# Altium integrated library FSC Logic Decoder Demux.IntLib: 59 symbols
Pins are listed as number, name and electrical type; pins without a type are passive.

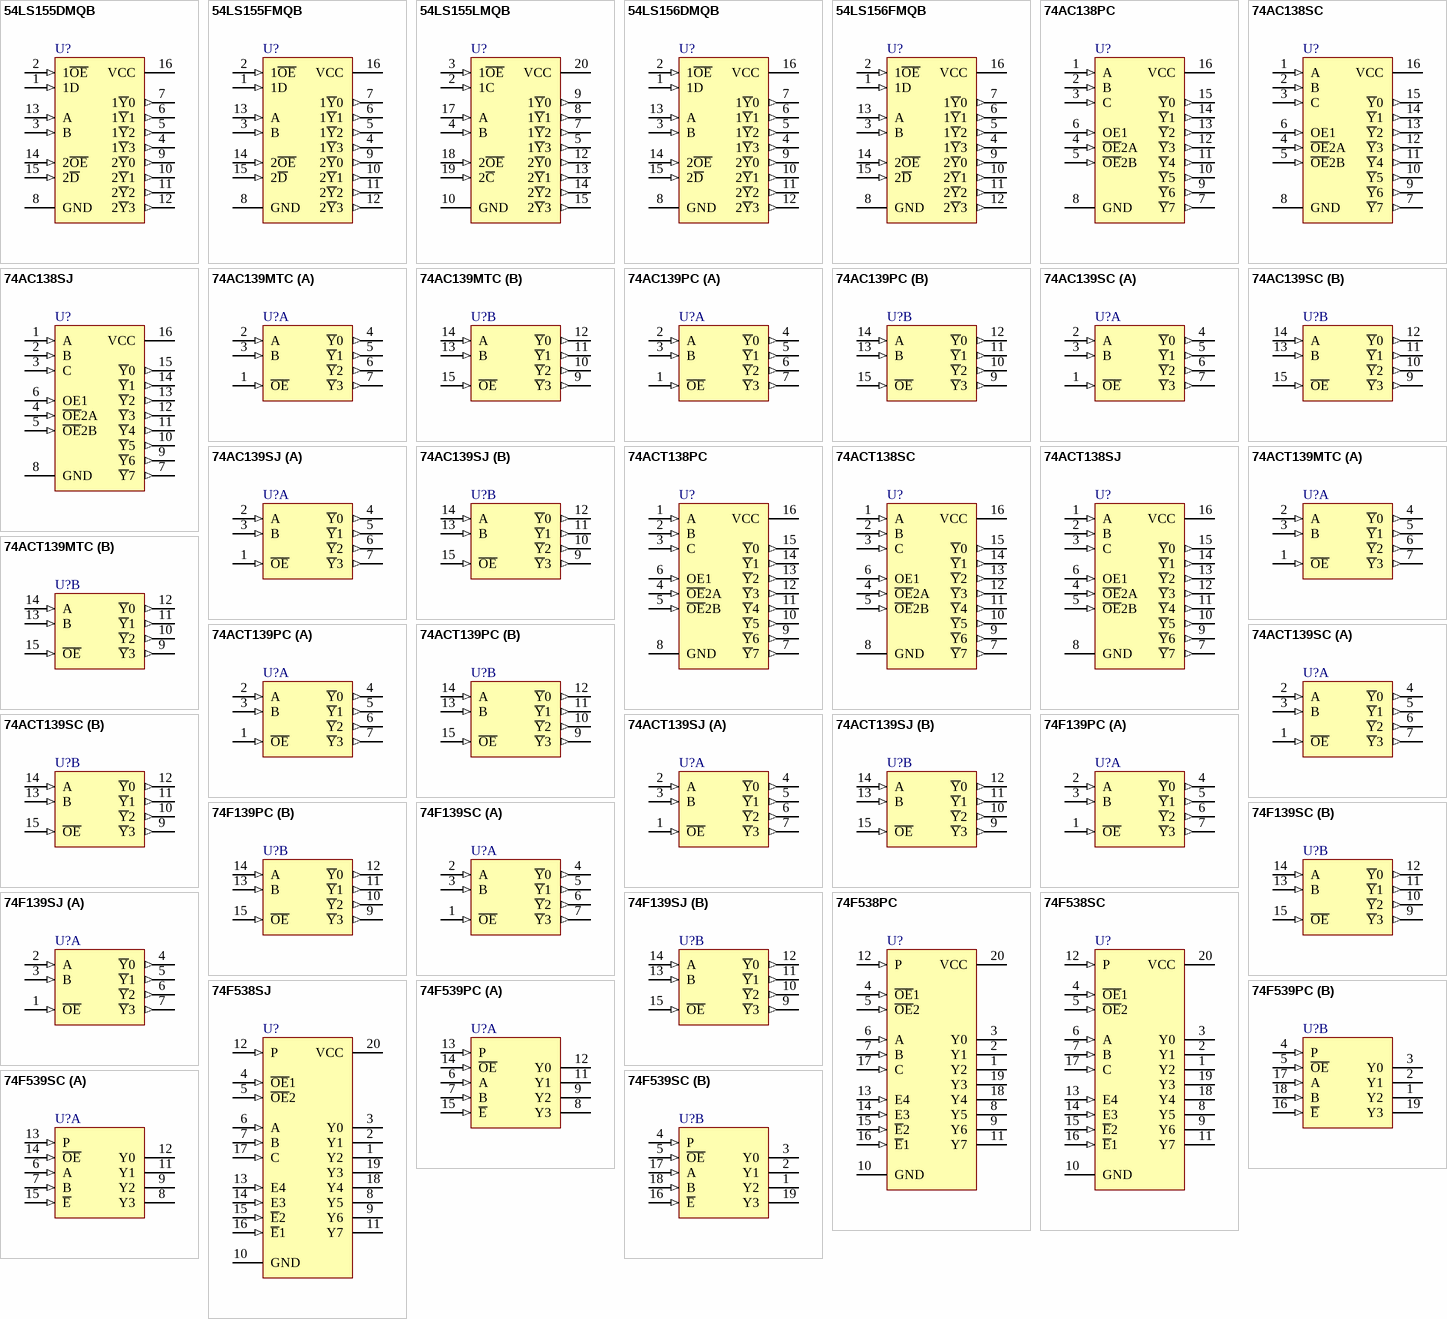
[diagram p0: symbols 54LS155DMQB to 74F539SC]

## 54LS155DMQB
designator U?
Dual 2-Line to 4-Line Decoder/Demultiplexer; Note: Generic Simulation model provided.
footprint J16A (DIP, 16-Leads, Row Spacing 7.62mm, Pitch 2.54mm, Body 19.56x6.73mm)
3D model N16E (CerDIP, 16-Pin, Row Spacing 7.62 mm, Pitch 2.54 mm)
simulation model 74LS155 (SIMCODE)
signal-integrity model 54LS155DMQB
pins: 1 1D (in), 2 1~{OE} (in), 3 B (in), 4 1~{Y}3 (out), 5 1~{Y}2 (out), 6 1~{Y}1 (out), 7 1~{Y}0 (out), 8 GND (power), 9 2~{Y}0 (out), 10 2~{Y}1 (out), 11 2~{Y}2 (out), 12 2~{Y}3 (out), 13 A (in), 14 2~{OE} (in), 15 2~{D} (in), 16 VCC (power)

## 54LS155FMQB
designator U?
Dual 2-Line to 4-Line Decoder/Demultiplexer; Note: Generic Simulation model provided.
footprint W16A (DFP; 16 Leads; Body 9.9 x 7.6 mm (LxW max); Pitch 1.27 mm)
3D model W16A (DFP; 16 Leads; Body 9.9 x 7.6 mm (LxW max); Pitch 1.27 mm)
simulation model 74LS155 (SIMCODE)
signal-integrity model 54LS155FMQB
pins: 1 1D (in), 2 1~{OE} (in), 3 B (in), 4 1~{Y}3 (out), 5 1~{Y}2 (out), 6 1~{Y}1 (out), 7 1~{Y}0 (out), 8 GND (power), 9 2~{Y}0 (out), 10 2~{Y}1 (out), 11 2~{Y}2 (out), 12 2~{Y}3 (out), 13 A (in), 14 2~{OE} (in), 15 2~{D} (in), 16 VCC (power)

## 54LS155LMQB
designator U?
Dual 2-Line to 4-Line Decoder/Demultiplexer; Note: Pins 1, 6, 11, and 16 are 'No Connect'.
footprint E20A (Leadless Chip Carrier; 20 Terminals; Body 8.9 x 8.9 mm)
footprint E20A_N (Leadless Chip Carrier, 20-Leads, Body 8.9x8.9mm, Pitch 1.27mm, IPC Medium Density)
footprint E20A_L (Leadless Chip Carrier, 20-Leads, Body 8.9x8.9mm, Pitch 1.27mm, IPC High Density)
footprint E20A_M (Leadless Chip Carrier, 20-Leads, Body 8.9x8.9mm, Pitch 1.27mm, IPC Low Density)
simulation model 74LS155 (SIMCODE)
signal-integrity model 54LS155LMQB
pins: 2 1C (in), 3 1~{OE} (in), 4 B (in), 5 1~{Y}3 (out), 7 1~{Y}2 (out), 8 1~{Y}1 (out), 9 1~{Y}0 (out), 10 GND (power), 12 2~{Y}0 (out), 13 2~{Y}1 (out), 14 2~{Y}2 (out), 15 2~{Y}3 (out), 17 A (in), 18 2~{OE} (in), 19 2~{C} (in), 20 VCC (power)

## 54LS156DMQB
designator U?
Dual 2-Line to 4-Line Decoder/Demultiplexer; Note: Generic Simulation model provided.
footprint J16A (DIP, 16-Leads, Row Spacing 7.62mm, Pitch 2.54mm, Body 19.56x6.73mm)
3D model N16E (CerDIP, 16-Pin, Row Spacing 7.62 mm, Pitch 2.54 mm)
simulation model 74LS156 (SIMCODE)
signal-integrity model 54LS156DMQB
pins: 1 1D (in), 2 1~{OE} (in), 3 B (in), 4 1~{Y}3 (out), 5 1~{Y}2 (out), 6 1~{Y}1 (out), 7 1~{Y}0 (out), 8 GND (power), 9 2~{Y}0 (out), 10 2~{Y}1 (out), 11 2~{Y}2 (out), 12 2~{Y}3 (out), 13 A (in), 14 2~{OE} (in), 15 2~{D} (in), 16 VCC (power)

## 54LS156FMQB
designator U?
Dual 2-Line to 4-Line Decoder/Demultiplexer; Note: Generic Simulation model provided.
footprint W16A (DFP; 16 Leads; Body 9.9 x 7.6 mm (LxW max); Pitch 1.27 mm)
3D model W16A (DFP; 16 Leads; Body 9.9 x 7.6 mm (LxW max); Pitch 1.27 mm)
simulation model 74LS156 (SIMCODE)
signal-integrity model 54LS156FMQB
pins: 1 1D (in), 2 1~{OE} (in), 3 B (in), 4 1~{Y}3 (out), 5 1~{Y}2 (out), 6 1~{Y}1 (out), 7 1~{Y}0 (out), 8 GND (power), 9 2~{Y}0 (out), 10 2~{Y}1 (out), 11 2~{Y}2 (out), 12 2~{Y}3 (out), 13 A (in), 14 2~{OE} (in), 15 2~{D} (in), 16 VCC (power)

## 74AC138PC
designator U?
1-of-8 Decoder/Multiplexer
footprint N16E (DIP, 16-Leads, Row Spacing 7.62mm, Pitch 2.54mm, Body 19.3x6.35mm)
3D model N16E (DIP, 16-Pin, Row Spacing 7.62 mm, Pitch 2.54 mm)
signal-integrity model 74AC138PC
pins: 1 A (in), 2 B (in), 3 C (in), 4 ~{OE}2A (in), 5 ~{OE}2B (in), 6 OE1 (in), 7 ~{Y}7 (out), 8 GND (power), 9 ~{Y}6 (out), 10 ~{Y}5 (out), 11 ~{Y}4 (out), 12 ~{Y}3 (out), 13 ~{Y}2 (out), 14 ~{Y}1 (out), 15 ~{Y}0 (out), 16 VCC (power)

## 74AC138SC
designator U?
1-of-8 Decoder/Multiplexer
footprint M16A_N (SOIC, 16-Leads, Body 9.9x3.9mm, Pitch 1.27mm, IPC Medium Density)
footprint M16A_L (SOIC, 16-Leads, Body 9.9x3.9mm, Pitch 1.27mm, IPC High Density)
footprint M16A_M (SOIC, 16-Leads, Body 9.9x3.9mm, Pitch 1.27mm, IPC Low Density)
3D model M16A (16-Pin Small Outline Integrated Circuit 1.27 mm Pitch)
signal-integrity model 74AC138SC
pins: 1 A (in), 2 B (in), 3 C (in), 4 ~{OE}2A (in), 5 ~{OE}2B (in), 6 OE1 (in), 7 ~{Y}7 (out), 8 GND (power), 9 ~{Y}6 (out), 10 ~{Y}5 (out), 11 ~{Y}4 (out), 12 ~{Y}3 (out), 13 ~{Y}2 (out), 14 ~{Y}1 (out), 15 ~{Y}0 (out), 16 VCC (power)

## 74AC138SJ
designator U?
1-of-8 Decoder/Multiplexer
footprint M16D_N (SOP, 16-Leads, Body 10.1x5.3mm, Pitch 1.27mm, IPC Medium Density)
footprint M16D_L (SOP, 16-Leads, Body 10.1x5.3mm, Pitch 1.27mm, IPC High Density)
footprint M16D_M (SOP, 16-Leads, Body 10.1x5.3mm, Pitch 1.27mm, IPC Low Density)
3D model M16D (16-Pin Small Outline Package 1.27 mm Pitch)
signal-integrity model 74AC138SJ
pins: 1 A (in), 2 B (in), 3 C (in), 4 ~{OE}2A (in), 5 ~{OE}2B (in), 6 OE1 (in), 7 ~{Y}7 (out), 8 GND (power), 9 ~{Y}6 (out), 10 ~{Y}5 (out), 11 ~{Y}4 (out), 12 ~{Y}3 (out), 13 ~{Y}2 (out), 14 ~{Y}1 (out), 15 ~{Y}0 (out), 16 VCC (power)

## 74AC139MTC
designator U?
Dual 1-of-4 Decoder/Demultiplexer; Note: Generic Simulation model provided.
footprint MTC16_N (TSOP, 16-Leads, Body 5x4.4mm, Pitch 0.65mm, IPC Medium Density)
footprint MTC16_L (TSOP, 16-Leads, Body 5x4.4mm, Pitch 0.65mm, IPC High Density)
footprint MTC16_M (TSOP, 16-Leads, Body 5x4.4mm, Pitch 0.65mm, IPC Low Density)
3D model MTC16 (16-Pin Thin Small Outline Package 0.65 mm Pitch)
simulation model 74LS139 (SIMCODE)
signal-integrity model 74AC139MTC
pins on every part: 8 GND (power) hidden to GND, 16 VCC (power) hidden to VCC
part A pins: 1 ~{OE} (in), 2 A (in), 3 B (in), 4 ~{Y}0 (out), 5 ~{Y}1 (out), 6 ~{Y}2 (out), 7 ~{Y}3 (out)
part B pins: 9 ~{Y}3 (out), 10 ~{Y}2 (out), 11 ~{Y}1 (out), 12 ~{Y}0 (out), 13 B (in), 14 A (in), 15 ~{OE} (in)

## 74AC139PC
designator U?
Dual 1-of-4 Decoder/Demultiplexer; Note: Generic Simulation model provided.
footprint N16E (DIP, 16-Leads, Row Spacing 7.62mm, Pitch 2.54mm, Body 19.3x6.35mm)
3D model N16E (DIP, 16-Pin, Row Spacing 7.62 mm, Pitch 2.54 mm)
simulation model 74LS139 (SIMCODE)
signal-integrity model 74AC139PC
pins on every part: 8 GND (power) hidden to GND, 16 VCC (power) hidden to VCC
part A pins: 1 ~{OE} (in), 2 A (in), 3 B (in), 4 ~{Y}0 (out), 5 ~{Y}1 (out), 6 ~{Y}2 (out), 7 ~{Y}3 (out)
part B pins: 9 ~{Y}3 (out), 10 ~{Y}2 (out), 11 ~{Y}1 (out), 12 ~{Y}0 (out), 13 B (in), 14 A (in), 15 ~{OE} (in)

## 74AC139SC
designator U?
Dual 1-of-4 Decoder/Demultiplexer; Note: Generic Simulation model provided.
footprint M16A_N (SOIC, 16-Leads, Body 9.9x3.9mm, Pitch 1.27mm, IPC Medium Density)
footprint M16A_L (SOIC, 16-Leads, Body 9.9x3.9mm, Pitch 1.27mm, IPC High Density)
footprint M16A_M (SOIC, 16-Leads, Body 9.9x3.9mm, Pitch 1.27mm, IPC Low Density)
3D model M16A (16-Pin Small Outline Integrated Circuit 1.27 mm Pitch)
simulation model 74LS139 (SIMCODE)
signal-integrity model 74AC139SC
pins on every part: 8 GND (power) hidden to GND, 16 VCC (power) hidden to VCC
part A pins: 1 ~{OE} (in), 2 A (in), 3 B (in), 4 ~{Y}0 (out), 5 ~{Y}1 (out), 6 ~{Y}2 (out), 7 ~{Y}3 (out)
part B pins: 9 ~{Y}3 (out), 10 ~{Y}2 (out), 11 ~{Y}1 (out), 12 ~{Y}0 (out), 13 B (in), 14 A (in), 15 ~{OE} (in)

## 74AC139SJ
designator U?
Dual 1-of-4 Decoder/Demultiplexer; Note: Generic Simulation model provided.
footprint M16D_N (SOP, 16-Leads, Body 10.1x5.3mm, Pitch 1.27mm, IPC Medium Density)
footprint M16D_L (SOP, 16-Leads, Body 10.1x5.3mm, Pitch 1.27mm, IPC High Density)
footprint M16D_M (SOP, 16-Leads, Body 10.1x5.3mm, Pitch 1.27mm, IPC Low Density)
3D model M16D (16-Pin Small Outline Package 1.27 mm Pitch)
simulation model 74LS139 (SIMCODE)
signal-integrity model 74AC139SJ
pins on every part: 8 GND (power) hidden to GND, 16 VCC (power) hidden to VCC
part A pins: 1 ~{OE} (in), 2 A (in), 3 B (in), 4 ~{Y}0 (out), 5 ~{Y}1 (out), 6 ~{Y}2 (out), 7 ~{Y}3 (out)
part B pins: 9 ~{Y}3 (out), 10 ~{Y}2 (out), 11 ~{Y}1 (out), 12 ~{Y}0 (out), 13 B (in), 14 A (in), 15 ~{OE} (in)

## 74ACT138PC
designator U?
1-of-8 Decoder/Multiplexer
footprint N16E (DIP, 16-Leads, Row Spacing 7.62mm, Pitch 2.54mm, Body 19.3x6.35mm)
3D model N16E (DIP, 16-Pin, Row Spacing 7.62 mm, Pitch 2.54 mm)
signal-integrity model 74ACT138PC
pins: 1 A (in), 2 B (in), 3 C (in), 4 ~{OE}2A (in), 5 ~{OE}2B (in), 6 OE1 (in), 7 ~{Y}7 (out), 8 GND (power), 9 ~{Y}6 (out), 10 ~{Y}5 (out), 11 ~{Y}4 (out), 12 ~{Y}3 (out), 13 ~{Y}2 (out), 14 ~{Y}1 (out), 15 ~{Y}0 (out), 16 VCC (power)

## 74ACT138SC
designator U?
1-of-8 Decoder/Multiplexer
footprint M16A_N (SOIC, 16-Leads, Body 9.9x3.9mm, Pitch 1.27mm, IPC Medium Density)
footprint M16A_L (SOIC, 16-Leads, Body 9.9x3.9mm, Pitch 1.27mm, IPC High Density)
footprint M16A_M (SOIC, 16-Leads, Body 9.9x3.9mm, Pitch 1.27mm, IPC Low Density)
3D model M16A (16-Pin Small Outline Integrated Circuit 1.27 mm Pitch)
signal-integrity model 74ACT138SC
pins: 1 A (in), 2 B (in), 3 C (in), 4 ~{OE}2A (in), 5 ~{OE}2B (in), 6 OE1 (in), 7 ~{Y}7 (out), 8 GND (power), 9 ~{Y}6 (out), 10 ~{Y}5 (out), 11 ~{Y}4 (out), 12 ~{Y}3 (out), 13 ~{Y}2 (out), 14 ~{Y}1 (out), 15 ~{Y}0 (out), 16 VCC (power)

## 74ACT138SJ
designator U?
1-of-8 Decoder/Multiplexer
footprint M16D_N (SOP, 16-Leads, Body 10.1x5.3mm, Pitch 1.27mm, IPC Medium Density)
footprint M16D_L (SOP, 16-Leads, Body 10.1x5.3mm, Pitch 1.27mm, IPC High Density)
footprint M16D_M (SOP, 16-Leads, Body 10.1x5.3mm, Pitch 1.27mm, IPC Low Density)
3D model M16D (16-Pin Small Outline Package 1.27 mm Pitch)
signal-integrity model 74ACT138SJ
pins: 1 A (in), 2 B (in), 3 C (in), 4 ~{OE}2A (in), 5 ~{OE}2B (in), 6 OE1 (in), 7 ~{Y}7 (out), 8 GND (power), 9 ~{Y}6 (out), 10 ~{Y}5 (out), 11 ~{Y}4 (out), 12 ~{Y}3 (out), 13 ~{Y}2 (out), 14 ~{Y}1 (out), 15 ~{Y}0 (out), 16 VCC (power)

## 74ACT139MTC
designator U?
Dual 1-of-4 Decoder/Demultiplexer; Note: Generic Simulation model provided.
footprint MTC16_N (TSOP, 16-Leads, Body 5x4.4mm, Pitch 0.65mm, IPC Medium Density)
footprint MTC16_L (TSOP, 16-Leads, Body 5x4.4mm, Pitch 0.65mm, IPC High Density)
footprint MTC16_M (TSOP, 16-Leads, Body 5x4.4mm, Pitch 0.65mm, IPC Low Density)
3D model MTC16 (16-Pin Thin Small Outline Package 0.65 mm Pitch)
simulation model 74LS139 (SIMCODE)
signal-integrity model 74ACT139MTC
pins on every part: 8 GND (power) hidden to GND, 16 VCC (power) hidden to VCC
part A pins: 1 ~{OE} (in), 2 A (in), 3 B (in), 4 ~{Y}0 (out), 5 ~{Y}1 (out), 6 ~{Y}2 (out), 7 ~{Y}3 (out)
part B pins: 9 ~{Y}3 (out), 10 ~{Y}2 (out), 11 ~{Y}1 (out), 12 ~{Y}0 (out), 13 B (in), 14 A (in), 15 ~{OE} (in)

## 74ACT139PC
designator U?
Dual 1-of-4 Decoder/Demultiplexer; Note: Generic Simulation model provided.
footprint N16E (DIP, 16-Leads, Row Spacing 7.62mm, Pitch 2.54mm, Body 19.3x6.35mm)
3D model N16E (DIP, 16-Pin, Row Spacing 7.62 mm, Pitch 2.54 mm)
simulation model 74LS139 (SIMCODE)
signal-integrity model 74ACT139PC
pins on every part: 8 GND (power) hidden to GND, 16 VCC (power) hidden to VCC
part A pins: 1 ~{OE} (in), 2 A (in), 3 B (in), 4 ~{Y}0 (out), 5 ~{Y}1 (out), 6 ~{Y}2 (out), 7 ~{Y}3 (out)
part B pins: 9 ~{Y}3 (out), 10 ~{Y}2 (out), 11 ~{Y}1 (out), 12 ~{Y}0 (out), 13 B (in), 14 A (in), 15 ~{OE} (in)

## 74ACT139SC
designator U?
Dual 1-of-4 Decoder/Demultiplexer; Note: Generic Simulation model provided.
footprint M16A_N (SOIC, 16-Leads, Body 9.9x3.9mm, Pitch 1.27mm, IPC Medium Density)
footprint M16A_L (SOIC, 16-Leads, Body 9.9x3.9mm, Pitch 1.27mm, IPC High Density)
footprint M16A_M (SOIC, 16-Leads, Body 9.9x3.9mm, Pitch 1.27mm, IPC Low Density)
3D model M16A (16-Pin Small Outline Integrated Circuit 1.27 mm Pitch)
simulation model 74LS139 (SIMCODE)
signal-integrity model 74ACT139SC
pins on every part: 8 GND (power) hidden to GND, 16 VCC (power) hidden to VCC
part A pins: 1 ~{OE} (in), 2 A (in), 3 B (in), 4 ~{Y}0 (out), 5 ~{Y}1 (out), 6 ~{Y}2 (out), 7 ~{Y}3 (out)
part B pins: 9 ~{Y}3 (out), 10 ~{Y}2 (out), 11 ~{Y}1 (out), 12 ~{Y}0 (out), 13 B (in), 14 A (in), 15 ~{OE} (in)

## 74ACT139SJ
designator U?
Dual 1-of-4 Decoder/Demultiplexer; Note: Generic Simulation model provided.
footprint M16D_N (SOP, 16-Leads, Body 10.1x5.3mm, Pitch 1.27mm, IPC Medium Density)
footprint M16D_L (SOP, 16-Leads, Body 10.1x5.3mm, Pitch 1.27mm, IPC High Density)
footprint M16D_M (SOP, 16-Leads, Body 10.1x5.3mm, Pitch 1.27mm, IPC Low Density)
3D model M16D (16-Pin Small Outline Package 1.27 mm Pitch)
simulation model 74LS139 (SIMCODE)
signal-integrity model 74ACT139SJ
pins on every part: 8 GND (power) hidden to GND, 16 VCC (power) hidden to VCC
part A pins: 1 ~{OE} (in), 2 A (in), 3 B (in), 4 ~{Y}0 (out), 5 ~{Y}1 (out), 6 ~{Y}2 (out), 7 ~{Y}3 (out)
part B pins: 9 ~{Y}3 (out), 10 ~{Y}2 (out), 11 ~{Y}1 (out), 12 ~{Y}0 (out), 13 B (in), 14 A (in), 15 ~{OE} (in)

## 74F139PC
designator U?
Dual 1-of-4 Decoder/Demultiplexer; Note: Generic Simulation model provided.
footprint N16E (DIP, 16-Leads, Row Spacing 7.62mm, Pitch 2.54mm, Body 19.3x6.35mm)
3D model N16E (DIP, 16-Pin, Row Spacing 7.62 mm, Pitch 2.54 mm)
simulation model 74LS139 (SIMCODE)
signal-integrity model 74F139PC
pins on every part: 8 GND (power) hidden to GND, 16 VCC (power) hidden to VCC
part A pins: 1 ~{OE} (in), 2 A (in), 3 B (in), 4 ~{Y}0 (out), 5 ~{Y}1 (out), 6 ~{Y}2 (out), 7 ~{Y}3 (out)
part B pins: 9 ~{Y}3 (out), 10 ~{Y}2 (out), 11 ~{Y}1 (out), 12 ~{Y}0 (out), 13 B (in), 14 A (in), 15 ~{OE} (in)

## 74F139SC
designator U?
Dual 1-of-4 Decoder/Demultiplexer; Note: Generic Simulation model provided.
footprint M16A_N (SOIC, 16-Leads, Body 9.9x3.9mm, Pitch 1.27mm, IPC Medium Density)
footprint M16A_L (SOIC, 16-Leads, Body 9.9x3.9mm, Pitch 1.27mm, IPC High Density)
footprint M16A_M (SOIC, 16-Leads, Body 9.9x3.9mm, Pitch 1.27mm, IPC Low Density)
3D model M16A (16-Pin Small Outline Integrated Circuit 1.27 mm Pitch)
simulation model 74LS139 (SIMCODE)
signal-integrity model 74F139SC
pins on every part: 8 GND (power) hidden to GND, 16 VCC (power) hidden to VCC
part A pins: 1 ~{OE} (in), 2 A (in), 3 B (in), 4 ~{Y}0 (out), 5 ~{Y}1 (out), 6 ~{Y}2 (out), 7 ~{Y}3 (out)
part B pins: 9 ~{Y}3 (out), 10 ~{Y}2 (out), 11 ~{Y}1 (out), 12 ~{Y}0 (out), 13 B (in), 14 A (in), 15 ~{OE} (in)

## 74F139SJ
designator U?
Dual 1-of-4 Decoder/Demultiplexer; Note: Generic Simulation model provided.
footprint M16D_N (SOP, 16-Leads, Body 10.1x5.3mm, Pitch 1.27mm, IPC Medium Density)
footprint M16D_L (SOP, 16-Leads, Body 10.1x5.3mm, Pitch 1.27mm, IPC High Density)
footprint M16D_M (SOP, 16-Leads, Body 10.1x5.3mm, Pitch 1.27mm, IPC Low Density)
3D model M16D (16-Pin Small Outline Package 1.27 mm Pitch)
simulation model 74LS139 (SIMCODE)
signal-integrity model 74F139SJ
pins on every part: 8 GND (power) hidden to GND, 16 VCC (power) hidden to VCC
part A pins: 1 ~{OE} (in), 2 A (in), 3 B (in), 4 ~{Y}0 (out), 5 ~{Y}1 (out), 6 ~{Y}2 (out), 7 ~{Y}3 (out)
part B pins: 9 ~{Y}3 (out), 10 ~{Y}2 (out), 11 ~{Y}1 (out), 12 ~{Y}0 (out), 13 B (in), 14 A (in), 15 ~{OE} (in)

## 74F538PC
designator U?
1-of-8 Decoder with 3-State Output
footprint N20A (DIP, 20-Leads, Row Spacing 7.62mm, Pitch 2.54mm, Body 26.07x6.6mm)
3D model N20A (DIP, 20-Pin, Row Spacing 7.62 mm, Pitch 2.54 mm)
signal-integrity model 74F538PC
pins: 1 Y2 (hiz), 2 Y1 (hiz), 3 Y0 (hiz), 4 ~{OE}1 (in), 5 ~{OE}2 (in), 6 A (in), 7 B (in), 8 Y5 (hiz), 9 Y6 (hiz), 10 GND (power), 11 Y7 (hiz), 12 P (in), 13 E4 (in), 14 E3 (in), 15 ~{E}2 (in), 16 ~{E}1 (in), 17 C (in), 18 Y4 (hiz), 19 Y3 (hiz), 20 VCC (power)

## 74F538SC
designator U?
1-of-8 Decoder with 3-State Output
footprint M20B_N (SOIC, 20-Leads, Body 12.8x7.5mm, Pitch 1.27mm, IPC Medium Density)
footprint M20B_L (SOIC, 20-Leads, Body 12.8x7.5mm, Pitch 1.27mm, IPC High Density)
footprint M20B_M (SOIC, 20-Leads, Body 12.8x7.5mm, Pitch 1.27mm, IPC Low Density)
3D model M20B (20-Pin Small Outline Integrated Circuit 1.27 mm Pitch)
signal-integrity model 74F538SC
pins: 1 Y2 (hiz), 2 Y1 (hiz), 3 Y0 (hiz), 4 ~{OE}1 (in), 5 ~{OE}2 (in), 6 A (in), 7 B (in), 8 Y5 (hiz), 9 Y6 (hiz), 10 GND (power), 11 Y7 (hiz), 12 P (in), 13 E4 (in), 14 E3 (in), 15 ~{E}2 (in), 16 ~{E}1 (in), 17 C (in), 18 Y4 (hiz), 19 Y3 (hiz), 20 VCC (power)

## 74F538SJ
designator U?
1-of-8 Decoder with 3-State Output
footprint M20D_N (SOP, 20-Leads, Body 12.6x5.3mm, Pitch 1.27mm, IPC Medium Density)
footprint M20D_L (SOP, 20-Leads, Body 12.6x5.3mm, Pitch 1.27mm, IPC High Density)
footprint M20D_M (SOP, 20-Leads, Body 12.6x5.3mm, Pitch 1.27mm, IPC Low Density)
3D model M20D (20-Pin Small Outline Package 1.27 mm Pitch)
signal-integrity model 74F538SJ
pins: 1 Y2 (hiz), 2 Y1 (hiz), 3 Y0 (hiz), 4 ~{OE}1 (in), 5 ~{OE}2 (in), 6 A (in), 7 B (in), 8 Y5 (hiz), 9 Y6 (hiz), 10 GND (power), 11 Y7 (hiz), 12 P (in), 13 E4 (in), 14 E3 (in), 15 ~{E}2 (in), 16 ~{E}1 (in), 17 C (in), 18 Y4 (hiz), 19 Y3 (hiz), 20 VCC (power)

## 74F539PC
designator U?
Dual 1-of-4 Decoder with 3-State Output
footprint N20A (DIP, 20-Leads, Row Spacing 7.62mm, Pitch 2.54mm, Body 26.07x6.6mm)
3D model N20A (DIP, 20-Pin, Row Spacing 7.62 mm, Pitch 2.54 mm)
signal-integrity model 74F539PC
pins on every part: 10 GND (power) hidden to GND, 20 VCC (power) hidden to VCC
part A pins: 6 A (in), 7 B (in), 8 Y3 (hiz), 9 Y2 (hiz), 11 Y1 (hiz), 12 Y0 (hiz), 13 P (in), 14 ~{OE} (in), 15 ~{E} (in)
part B pins: 1 Y2 (hiz), 2 Y1 (hiz), 3 Y0 (hiz), 4 P (in), 5 ~{OE} (in), 16 ~{E} (in), 17 A (in), 18 B (in), 19 Y3 (hiz)

## 74F539SC
designator U?
Dual 1-of-4 Decoder with 3-State Output
footprint M20B_N (SOIC, 20-Leads, Body 12.8x7.5mm, Pitch 1.27mm, IPC Medium Density)
footprint M20B_L (SOIC, 20-Leads, Body 12.8x7.5mm, Pitch 1.27mm, IPC High Density)
footprint M20B_M (SOIC, 20-Leads, Body 12.8x7.5mm, Pitch 1.27mm, IPC Low Density)
3D model M20B (20-Pin Small Outline Integrated Circuit 1.27 mm Pitch)
signal-integrity model 74F539SC
pins on every part: 10 GND (power) hidden to GND, 20 VCC (power) hidden to VCC
part A pins: 6 A (in), 7 B (in), 8 Y3 (hiz), 9 Y2 (hiz), 11 Y1 (hiz), 12 Y0 (hiz), 13 P (in), 14 ~{OE} (in), 15 ~{E} (in)
part B pins: 1 Y2 (hiz), 2 Y1 (hiz), 3 Y0 (hiz), 4 P (in), 5 ~{OE} (in), 16 ~{E} (in), 17 A (in), 18 B (in), 19 Y3 (hiz)

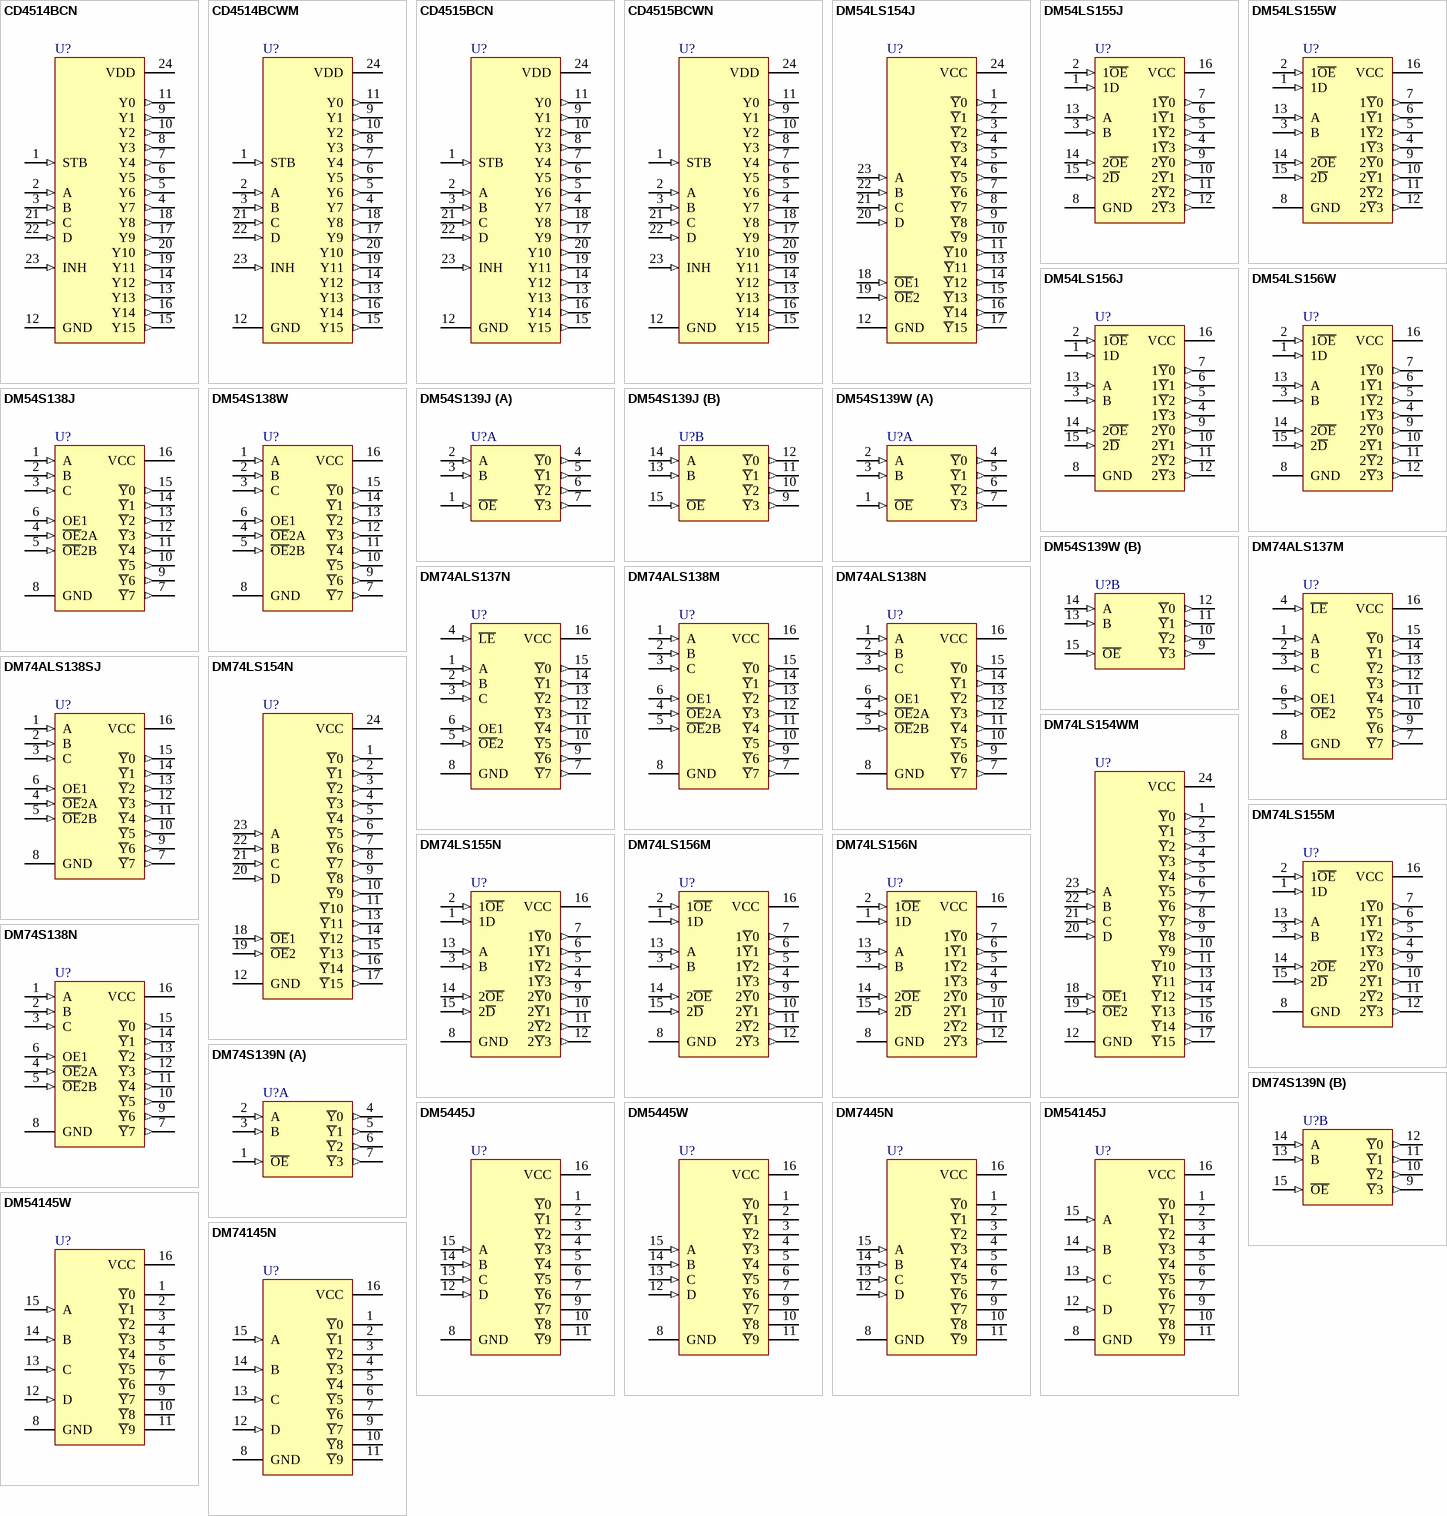
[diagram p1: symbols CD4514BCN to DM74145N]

## CD4514BCN
designator U?
4 Bit Latched/4-to-16-Line Decoder
footprint N24A (DIP, 24-Leads, Row Spacing 15.24mm, Pitch 2.54mm, Body 31.92x13.72mm)
3D model N24A (DIP, 24-Pin, Row Spacing 15.24 mm, Pitch 2.54 mm)
pins: 1 STB (in), 2 A (in), 3 B (in), 4 Y7 (out), 5 Y6 (out), 6 Y5 (out), 7 Y4 (out), 8 Y3 (out), 9 Y1 (out), 10 Y2 (out), 11 Y0 (out), 12 GND (power), 13 Y13 (out), 14 Y12 (out), 15 Y15 (out), 16 Y14 (out), 17 Y9 (out), 18 Y8 (out), 19 Y11 (out), 20 Y10 (out), 21 C (in), 22 D (in), 23 INH (in), 24 VDD (power)

## CD4514BCWM
designator U?
4 Bit Latched/4-to-16-Line Decoder
footprint M24B_N (SOIC, 24-Leads, Body 15.4x7.5mm, Pitch 1.27mm, IPC Medium Density)
footprint M24B_L (SOIC, 24-Leads, Body 15.4x7.5mm, Pitch 1.27mm, IPC High Density)
footprint M24B_M (SOIC, 24-Leads, Body 15.4x7.5mm, Pitch 1.27mm, IPC Low Density)
3D model M24B (24-Pin Small Outline Integrated Circuit 1.27 mm Pitch)
pins: 1 STB (in), 2 A (in), 3 B (in), 4 Y7 (out), 5 Y6 (out), 6 Y5 (out), 7 Y4 (out), 8 Y3 (out), 9 Y1 (out), 10 Y2 (out), 11 Y0 (out), 12 GND (power), 13 Y13 (out), 14 Y12 (out), 15 Y15 (out), 16 Y14 (out), 17 Y9 (out), 18 Y8 (out), 19 Y11 (out), 20 Y10 (out), 21 C (in), 22 D (in), 23 INH (in), 24 VDD (power)

## CD4515BCN
designator U?
4 Bit Latched/4-to-16-Line Decoder
footprint N24A (DIP, 24-Leads, Row Spacing 15.24mm, Pitch 2.54mm, Body 31.92x13.72mm)
3D model N24A (DIP, 24-Pin, Row Spacing 15.24 mm, Pitch 2.54 mm)
pins: 1 STB (in), 2 A (in), 3 B (in), 4 Y7 (out), 5 Y6 (out), 6 Y5 (out), 7 Y4 (out), 8 Y3 (out), 9 Y1 (out), 10 Y2 (out), 11 Y0 (out), 12 GND (power), 13 Y13 (out), 14 Y12 (out), 15 Y15 (out), 16 Y14 (out), 17 Y9 (out), 18 Y8 (out), 19 Y11 (out), 20 Y10 (out), 21 C (in), 22 D (in), 23 INH (in), 24 VDD (power)

## CD4515BCWN
designator U?
4 Bit Latched/4-to-16-Line Decoder
footprint M24B_N (SOIC, 24-Leads, Body 15.4x7.5mm, Pitch 1.27mm, IPC Medium Density)
footprint M24B_L (SOIC, 24-Leads, Body 15.4x7.5mm, Pitch 1.27mm, IPC High Density)
footprint M24B_M (SOIC, 24-Leads, Body 15.4x7.5mm, Pitch 1.27mm, IPC Low Density)
3D model M24B (24-Pin Small Outline Integrated Circuit 1.27 mm Pitch)
pins: 1 STB (in), 2 A (in), 3 B (in), 4 Y7 (out), 5 Y6 (out), 6 Y5 (out), 7 Y4 (out), 8 Y3 (out), 9 Y1 (out), 10 Y2 (out), 11 Y0 (out), 12 GND (power), 13 Y13 (out), 14 Y12 (out), 15 Y15 (out), 16 Y14 (out), 17 Y9 (out), 18 Y8 (out), 19 Y11 (out), 20 Y10 (out), 21 C (in), 22 D (in), 23 INH (in), 24 VDD (power)

## DM54LS154J
designator U?
4-Line to 16-Line Decoder/Demultiplexer; Note: Generic Simulation model provided.
footprint J24A (DIP, 24-Leads, Row Spacing 15.24mm, Pitch 2.54mm, Body 31.75x13.21mm)
3D model N24A (CerDIP, 24-Pin, Row Spacing 15.24 mm, Pitch 2.54 mm)
simulation model 74LS154 (SIMCODE)
signal-integrity model DM54LS154J
pins: 1 ~{Y}0 (out), 2 ~{Y}1 (out), 3 ~{Y}2 (out), 4 ~{Y}3 (out), 5 ~{Y}4 (out), 6 ~{Y}5 (out), 7 ~{Y}6 (out), 8 ~{Y}7 (out), 9 ~{Y}8 (out), 10 ~{Y}9 (out), 11 ~{Y}10 (out), 12 GND (power), 13 ~{Y}11 (out), 14 ~{Y}12 (out), 15 ~{Y}13 (out), 16 ~{Y}14 (out), 17 ~{Y}15 (out), 18 ~{OE}1 (in), 19 ~{OE}2 (in), 20 D (in), 21 C (in), 22 B (in), 23 A (in), 24 VCC (power)

## DM54LS155J
designator U?
Dual 2-Line to 4-Line Decoder/Demultiplexer; Note: Generic Simulation model provided.
footprint J16A (DIP, 16-Leads, Row Spacing 7.62mm, Pitch 2.54mm, Body 19.56x6.73mm)
3D model N16E (CerDIP, 16-Pin, Row Spacing 7.62 mm, Pitch 2.54 mm)
simulation model 74LS155 (SIMCODE)
signal-integrity model DM54LS155J
pins: 1 1D (in), 2 1~{OE} (in), 3 B (in), 4 1~{Y}3 (out), 5 1~{Y}2 (out), 6 1~{Y}1 (out), 7 1~{Y}0 (out), 8 GND (power), 9 2~{Y}0 (out), 10 2~{Y}1 (out), 11 2~{Y}2 (out), 12 2~{Y}3 (out), 13 A (in), 14 2~{OE} (in), 15 2~{D} (in), 16 VCC (power)

## DM54LS155W
designator U?
Dual 2-Line to 4-Line Decoder/Demultiplexer; Note: Generic Simulation model provided.
footprint W16A (DFP; 16 Leads; Body 9.9 x 7.6 mm (LxW max); Pitch 1.27 mm)
3D model W16A (DFP; 16 Leads; Body 9.9 x 7.6 mm (LxW max); Pitch 1.27 mm)
simulation model 74LS155 (SIMCODE)
signal-integrity model DM54LS155W
pins: 1 1D (in), 2 1~{OE} (in), 3 B (in), 4 1~{Y}3 (out), 5 1~{Y}2 (out), 6 1~{Y}1 (out), 7 1~{Y}0 (out), 8 GND (power), 9 2~{Y}0 (out), 10 2~{Y}1 (out), 11 2~{Y}2 (out), 12 2~{Y}3 (out), 13 A (in), 14 2~{OE} (in), 15 2~{D} (in), 16 VCC (power)

## DM54LS156J
designator U?
Dual 2-Line to 4-Line Decoder/Demultiplexer; Note: Generic Simulation model provided.
footprint J16A (DIP, 16-Leads, Row Spacing 7.62mm, Pitch 2.54mm, Body 19.56x6.73mm)
3D model N16E (CerDIP, 16-Pin, Row Spacing 7.62 mm, Pitch 2.54 mm)
simulation model 74LS156 (SIMCODE)
signal-integrity model DM54LS156J
pins: 1 1D (in), 2 1~{OE} (in), 3 B (in), 4 1~{Y}3 (out), 5 1~{Y}2 (out), 6 1~{Y}1 (out), 7 1~{Y}0 (out), 8 GND (power), 9 2~{Y}0 (out), 10 2~{Y}1 (out), 11 2~{Y}2 (out), 12 2~{Y}3 (out), 13 A (in), 14 2~{OE} (in), 15 2~{D} (in), 16 VCC (power)

## DM54LS156W
designator U?
Dual 2-Line to 4-Line Decoder/Demultiplexer; Note: Generic Simulation model provided.
footprint W16A (DFP; 16 Leads; Body 9.9 x 7.6 mm (LxW max); Pitch 1.27 mm)
3D model W16A (DFP; 16 Leads; Body 9.9 x 7.6 mm (LxW max); Pitch 1.27 mm)
simulation model 74LS156 (SIMCODE)
signal-integrity model DM54LS156W
pins: 1 1D (in), 2 1~{OE} (in), 3 B (in), 4 1~{Y}3 (out), 5 1~{Y}2 (out), 6 1~{Y}1 (out), 7 1~{Y}0 (out), 8 GND (power), 9 2~{Y}0 (out), 10 2~{Y}1 (out), 11 2~{Y}2 (out), 12 2~{Y}3 (out), 13 A (in), 14 2~{OE} (in), 15 2~{D} (in), 16 VCC (power)

## DM54S138J
designator U?
3-to-8-Line Decoder; Note: Generic Simulation model provided.
footprint J16A (DIP, 16-Leads, Row Spacing 7.62mm, Pitch 2.54mm, Body 19.56x6.73mm)
3D model N16E (CerDIP, 16-Pin, Row Spacing 7.62 mm, Pitch 2.54 mm)
simulation model 74LS138 (SIMCODE)
signal-integrity model DM54S138J
pins: 1 A (in), 2 B (in), 3 C (in), 4 ~{OE}2A (in), 5 ~{OE}2B (in), 6 OE1 (in), 7 ~{Y}7 (out), 8 GND (power), 9 ~{Y}6 (out), 10 ~{Y}5 (out), 11 ~{Y}4 (out), 12 ~{Y}3 (out), 13 ~{Y}2 (out), 14 ~{Y}1 (out), 15 ~{Y}0 (out), 16 VCC (power)

## DM54S138W
designator U?
3-to-8-Line Decoder; Note: Generic Simulation model provided.
footprint W16A (DFP; 16 Leads; Body 9.9 x 7.6 mm (LxW max); Pitch 1.27 mm)
3D model W16A (DFP; 16 Leads; Body 9.9 x 7.6 mm (LxW max); Pitch 1.27 mm)
simulation model 74LS138 (SIMCODE)
signal-integrity model DM54S138W
pins: 1 A (in), 2 B (in), 3 C (in), 4 ~{OE}2A (in), 5 ~{OE}2B (in), 6 OE1 (in), 7 ~{Y}7 (out), 8 GND (power), 9 ~{Y}6 (out), 10 ~{Y}5 (out), 11 ~{Y}4 (out), 12 ~{Y}3 (out), 13 ~{Y}2 (out), 14 ~{Y}1 (out), 15 ~{Y}0 (out), 16 VCC (power)

## DM54S139J
designator U?
2-to-4-Line Decoder/Multiplexer; Note: Generic Simulation model provided.
footprint J16A (DIP, 16-Leads, Row Spacing 7.62mm, Pitch 2.54mm, Body 19.56x6.73mm)
3D model N16E (CerDIP, 16-Pin, Row Spacing 7.62 mm, Pitch 2.54 mm)
simulation model 74LS139 (SIMCODE)
signal-integrity model DM54S139J
pins on every part: 8 GND (power) hidden to GND, 16 VCC (power) hidden to VCC
part A pins: 1 ~{OE} (in), 2 A (in), 3 B (in), 4 ~{Y}0 (out), 5 ~{Y}1 (out), 6 ~{Y}2 (out), 7 ~{Y}3 (out)
part B pins: 9 ~{Y}3 (out), 10 ~{Y}2 (out), 11 ~{Y}1 (out), 12 ~{Y}0 (out), 13 B (in), 14 A (in), 15 ~{OE} (in)

## DM54S139W
designator U?
2-to-4-Line Decoder/Multiplexer; Note: Generic Simulation model provided.
footprint W16A (DFP; 16 Leads; Body 9.9 x 7.6 mm (LxW max); Pitch 1.27 mm)
3D model W16A (DFP; 16 Leads; Body 9.9 x 7.6 mm (LxW max); Pitch 1.27 mm)
simulation model 74LS139 (SIMCODE)
signal-integrity model DM54S139W
pins on every part: 8 GND (power) hidden to GND, 16 VCC (power) hidden to VCC
part A pins: 1 ~{OE} (in), 2 A (in), 3 B (in), 4 ~{Y}0 (out), 5 ~{Y}1 (out), 6 ~{Y}2 (out), 7 ~{Y}3 (out)
part B pins: 9 ~{Y}3 (out), 10 ~{Y}2 (out), 11 ~{Y}1 (out), 12 ~{Y}0 (out), 13 B (in), 14 A (in), 15 ~{OE} (in)

## DM74ALS137M
designator U?
3-to-8-Line Decoder/Demultiplexer with Address Latches
footprint M16A_N (SOIC, 16-Leads, Body 9.9x3.9mm, Pitch 1.27mm, IPC Medium Density)
footprint M16A_L (SOIC, 16-Leads, Body 9.9x3.9mm, Pitch 1.27mm, IPC High Density)
footprint M16A_M (SOIC, 16-Leads, Body 9.9x3.9mm, Pitch 1.27mm, IPC Low Density)
3D model M16A (16-Pin Small Outline Integrated Circuit 1.27 mm Pitch)
signal-integrity model DM74ALS137M
pins: 1 A (in), 2 B (in), 3 C (in), 4 ~{LE} (in), 5 ~{OE}2 (in), 6 OE1 (in), 7 ~{Y}7 (out), 8 GND (power), 9 ~{Y}6 (out), 10 ~{Y}5 (out), 11 ~{Y}4 (out), 12 ~{Y}3 (out), 13 ~{Y}2 (out), 14 ~{Y}1 (out), 15 ~{Y}0 (out), 16 VCC (power)

## DM74ALS137N
designator U?
3-to-8-Line Decoder/Demultiplexer with Address Latches
footprint N16A (DIP, 16-Leads, Row Spacing 7.62mm, Pitch 2.54mm, Body 21.76x6.35mm)
3D model N16A (DIP, 16-Pin, Row Spacing 7.62 mm, Pitch 2.54 mm)
signal-integrity model DM74ALS137N
pins: 1 A (in), 2 B (in), 3 C (in), 4 ~{LE} (in), 5 ~{OE}2 (in), 6 OE1 (in), 7 ~{Y}7 (out), 8 GND (power), 9 ~{Y}6 (out), 10 ~{Y}5 (out), 11 ~{Y}4 (out), 12 ~{Y}3 (out), 13 ~{Y}2 (out), 14 ~{Y}1 (out), 15 ~{Y}0 (out), 16 VCC (power)

## DM74ALS138M
designator U?
3-to-8-Line Decoder/Demultiplexer; Note: Generic Simulation model provided.
footprint M16A_N (SOIC, 16-Leads, Body 9.9x3.9mm, Pitch 1.27mm, IPC Medium Density)
footprint M16A_L (SOIC, 16-Leads, Body 9.9x3.9mm, Pitch 1.27mm, IPC High Density)
footprint M16A_M (SOIC, 16-Leads, Body 9.9x3.9mm, Pitch 1.27mm, IPC Low Density)
3D model M16A (16-Pin Small Outline Integrated Circuit 1.27 mm Pitch)
simulation model 74LS138 (SIMCODE)
signal-integrity model DM74ALS138M
pins: 1 A (in), 2 B (in), 3 C (in), 4 ~{OE}2A (in), 5 ~{OE}2B (in), 6 OE1 (in), 7 ~{Y}7 (out), 8 GND (power), 9 ~{Y}6 (out), 10 ~{Y}5 (out), 11 ~{Y}4 (out), 12 ~{Y}3 (out), 13 ~{Y}2 (out), 14 ~{Y}1 (out), 15 ~{Y}0 (out), 16 VCC (power)

## DM74ALS138N
designator U?
3-to-8-Line Decoder/Demultiplexer; Note: Generic Simulation model provided.
footprint N16A (DIP, 16-Leads, Row Spacing 7.62mm, Pitch 2.54mm, Body 21.76x6.35mm)
3D model N16A (DIP, 16-Pin, Row Spacing 7.62 mm, Pitch 2.54 mm)
simulation model 74LS138 (SIMCODE)
signal-integrity model DM74ALS138N
pins: 1 A (in), 2 B (in), 3 C (in), 4 ~{OE}2A (in), 5 ~{OE}2B (in), 6 OE1 (in), 7 ~{Y}7 (out), 8 GND (power), 9 ~{Y}6 (out), 10 ~{Y}5 (out), 11 ~{Y}4 (out), 12 ~{Y}3 (out), 13 ~{Y}2 (out), 14 ~{Y}1 (out), 15 ~{Y}0 (out), 16 VCC (power)

## DM74ALS138SJ
designator U?
3-to-8-Line Decoder/Demultiplexer; Note: Generic Simulation model provided.
footprint M16D_N (SOP, 16-Leads, Body 10.1x5.3mm, Pitch 1.27mm, IPC Medium Density)
footprint M16D_L (SOP, 16-Leads, Body 10.1x5.3mm, Pitch 1.27mm, IPC High Density)
footprint M16D_M (SOP, 16-Leads, Body 10.1x5.3mm, Pitch 1.27mm, IPC Low Density)
3D model M16D (16-Pin Small Outline Package 1.27 mm Pitch)
simulation model 74LS138 (SIMCODE)
signal-integrity model DM74ALS138SJ
pins: 1 A (in), 2 B (in), 3 C (in), 4 ~{OE}2A (in), 5 ~{OE}2B (in), 6 OE1 (in), 7 ~{Y}7 (out), 8 GND (power), 9 ~{Y}6 (out), 10 ~{Y}5 (out), 11 ~{Y}4 (out), 12 ~{Y}3 (out), 13 ~{Y}2 (out), 14 ~{Y}1 (out), 15 ~{Y}0 (out), 16 VCC (power)

## DM74LS154N
designator U?
4-Line to 16-Line Decoder/Demultiplexer; Note: Generic Simulation model provided.
footprint N24A (DIP, 24-Leads, Row Spacing 15.24mm, Pitch 2.54mm, Body 31.92x13.72mm)
3D model N24A (DIP, 24-Pin, Row Spacing 15.24 mm, Pitch 2.54 mm)
simulation model 74LS154 (SIMCODE)
signal-integrity model DM74LS154N
pins: 1 ~{Y}0 (out), 2 ~{Y}1 (out), 3 ~{Y}2 (out), 4 ~{Y}3 (out), 5 ~{Y}4 (out), 6 ~{Y}5 (out), 7 ~{Y}6 (out), 8 ~{Y}7 (out), 9 ~{Y}8 (out), 10 ~{Y}9 (out), 11 ~{Y}10 (out), 12 GND (power), 13 ~{Y}11 (out), 14 ~{Y}12 (out), 15 ~{Y}13 (out), 16 ~{Y}14 (out), 17 ~{Y}15 (out), 18 ~{OE}1 (in), 19 ~{OE}2 (in), 20 D (in), 21 C (in), 22 B (in), 23 A (in), 24 VCC (power)

## DM74LS154WM
designator U?
4-Line to 16-Line Decoder/Demultiplexer; Note: Generic Simulation model provided.
footprint M24B_N (SOIC, 24-Leads, Body 15.4x7.5mm, Pitch 1.27mm, IPC Medium Density)
footprint M24B_L (SOIC, 24-Leads, Body 15.4x7.5mm, Pitch 1.27mm, IPC High Density)
footprint M24B_M (SOIC, 24-Leads, Body 15.4x7.5mm, Pitch 1.27mm, IPC Low Density)
3D model M24B (24-Pin Small Outline Integrated Circuit 1.27 mm Pitch)
simulation model 74LS154 (SIMCODE)
signal-integrity model DM74LS154WM
pins: 1 ~{Y}0 (out), 2 ~{Y}1 (out), 3 ~{Y}2 (out), 4 ~{Y}3 (out), 5 ~{Y}4 (out), 6 ~{Y}5 (out), 7 ~{Y}6 (out), 8 ~{Y}7 (out), 9 ~{Y}8 (out), 10 ~{Y}9 (out), 11 ~{Y}10 (out), 12 GND (power), 13 ~{Y}11 (out), 14 ~{Y}12 (out), 15 ~{Y}13 (out), 16 ~{Y}14 (out), 17 ~{Y}15 (out), 18 ~{OE}1 (in), 19 ~{OE}2 (in), 20 D (in), 21 C (in), 22 B (in), 23 A (in), 24 VCC (power)

## DM74LS155M
designator U?
Dual 2-Line to 4-Line Decoder/Demultiplexer; Note: Generic Simulation model provided.
footprint M16A_N (SOIC, 16-Leads, Body 9.9x3.9mm, Pitch 1.27mm, IPC Medium Density)
footprint M16A_L (SOIC, 16-Leads, Body 9.9x3.9mm, Pitch 1.27mm, IPC High Density)
footprint M16A_M (SOIC, 16-Leads, Body 9.9x3.9mm, Pitch 1.27mm, IPC Low Density)
3D model M16A (16-Pin Small Outline Integrated Circuit 1.27 mm Pitch)
simulation model 74LS155 (SIMCODE)
signal-integrity model DM74LS155M
pins: 1 1D (in), 2 1~{OE} (in), 3 B (in), 4 1~{Y}3 (out), 5 1~{Y}2 (out), 6 1~{Y}1 (out), 7 1~{Y}0 (out), 8 GND (power), 9 2~{Y}0 (out), 10 2~{Y}1 (out), 11 2~{Y}2 (out), 12 2~{Y}3 (out), 13 A (in), 14 2~{OE} (in), 15 2~{D} (in), 16 VCC (power)

## DM74LS155N
designator U?
Dual 2-Line to 4-Line Decoder/Demultiplexer; Note: Generic Simulation model provided.
footprint N16E (DIP, 16-Leads, Row Spacing 7.62mm, Pitch 2.54mm, Body 19.3x6.35mm)
3D model N16E (DIP, 16-Pin, Row Spacing 7.62 mm, Pitch 2.54 mm)
simulation model 74LS155 (SIMCODE)
signal-integrity model DM74LS155N
pins: 1 1D (in), 2 1~{OE} (in), 3 B (in), 4 1~{Y}3 (out), 5 1~{Y}2 (out), 6 1~{Y}1 (out), 7 1~{Y}0 (out), 8 GND (power), 9 2~{Y}0 (out), 10 2~{Y}1 (out), 11 2~{Y}2 (out), 12 2~{Y}3 (out), 13 A (in), 14 2~{OE} (in), 15 2~{D} (in), 16 VCC (power)

## DM74LS156M
designator U?
Dual 2-Line to 4-Line Decoder/Demultiplexer; Note: Generic Simulation model provided.
footprint M16A_N (SOIC, 16-Leads, Body 9.9x3.9mm, Pitch 1.27mm, IPC Medium Density)
footprint M16A_L (SOIC, 16-Leads, Body 9.9x3.9mm, Pitch 1.27mm, IPC High Density)
footprint M16A_M (SOIC, 16-Leads, Body 9.9x3.9mm, Pitch 1.27mm, IPC Low Density)
3D model M16A (16-Pin Small Outline Integrated Circuit 1.27 mm Pitch)
simulation model 74LS156 (SIMCODE)
signal-integrity model DM74LS156M
pins: 1 1D (in), 2 1~{OE} (in), 3 B (in), 4 1~{Y}3 (out), 5 1~{Y}2 (out), 6 1~{Y}1 (out), 7 1~{Y}0 (out), 8 GND (power), 9 2~{Y}0 (out), 10 2~{Y}1 (out), 11 2~{Y}2 (out), 12 2~{Y}3 (out), 13 A (in), 14 2~{OE} (in), 15 2~{D} (in), 16 VCC (power)

## DM74LS156N
designator U?
Dual 2-Line to 4-Line Decoder/Demultiplexer; Note: Generic Simulation model provided.
footprint N16E (DIP, 16-Leads, Row Spacing 7.62mm, Pitch 2.54mm, Body 19.3x6.35mm)
3D model N16E (DIP, 16-Pin, Row Spacing 7.62 mm, Pitch 2.54 mm)
simulation model 74LS156 (SIMCODE)
signal-integrity model DM74LS156N
pins: 1 1D (in), 2 1~{OE} (in), 3 B (in), 4 1~{Y}3 (out), 5 1~{Y}2 (out), 6 1~{Y}1 (out), 7 1~{Y}0 (out), 8 GND (power), 9 2~{Y}0 (out), 10 2~{Y}1 (out), 11 2~{Y}2 (out), 12 2~{Y}3 (out), 13 A (in), 14 2~{OE} (in), 15 2~{D} (in), 16 VCC (power)

## DM74S138N
designator U?
3-to-8-Line Decoder; Note: Generic Simulation model provided.
footprint N16E (DIP, 16-Leads, Row Spacing 7.62mm, Pitch 2.54mm, Body 19.3x6.35mm)
3D model N16E (DIP, 16-Pin, Row Spacing 7.62 mm, Pitch 2.54 mm)
simulation model 74LS138 (SIMCODE)
signal-integrity model DM74S138N
pins: 1 A (in), 2 B (in), 3 C (in), 4 ~{OE}2A (in), 5 ~{OE}2B (in), 6 OE1 (in), 7 ~{Y}7 (out), 8 GND (power), 9 ~{Y}6 (out), 10 ~{Y}5 (out), 11 ~{Y}4 (out), 12 ~{Y}3 (out), 13 ~{Y}2 (out), 14 ~{Y}1 (out), 15 ~{Y}0 (out), 16 VCC (power)

## DM74S139N
designator U?
2-to-4-Line Decoder/Multiplexer; Note: Generic Simulation model provided.
footprint N16E (DIP, 16-Leads, Row Spacing 7.62mm, Pitch 2.54mm, Body 19.3x6.35mm)
3D model N16E (DIP, 16-Pin, Row Spacing 7.62 mm, Pitch 2.54 mm)
simulation model 74LS139 (SIMCODE)
signal-integrity model DM74S139N
pins on every part: 8 GND (power) hidden to GND, 16 VCC (power) hidden to VCC
part A pins: 1 ~{OE} (in), 2 A (in), 3 B (in), 4 ~{Y}0 (out), 5 ~{Y}1 (out), 6 ~{Y}2 (out), 7 ~{Y}3 (out)
part B pins: 9 ~{Y}3 (out), 10 ~{Y}2 (out), 11 ~{Y}1 (out), 12 ~{Y}0 (out), 13 B (in), 14 A (in), 15 ~{OE} (in)

## DM5445J
designator U?
BCD-To-Decimal Decoder/Driver; Note: Generic Simulation model provided.
footprint J16A (DIP, 16-Leads, Row Spacing 7.62mm, Pitch 2.54mm, Body 19.56x6.73mm)
3D model N16E (CerDIP, 16-Pin, Row Spacing 7.62 mm, Pitch 2.54 mm)
simulation model 7445 (SIMCODE)
signal-integrity model DM5445J
pins: 1 ~{Y}0 (oc), 2 ~{Y}1 (oc), 3 ~{Y}2 (oc), 4 ~{Y}3 (oc), 5 ~{Y}4 (oc), 6 ~{Y}5 (oc), 7 ~{Y}6 (oc), 8 GND (power), 9 ~{Y}7 (oc), 10 ~{Y}8 (oc), 11 ~{Y}9 (oc), 12 D (in), 13 C (in), 14 B (in), 15 A (in), 16 VCC (power)

## DM5445W
designator U?
BCD-To-Decimal Decoder/Driver; Note: Generic Simulation model provided.
footprint W16A (DFP; 16 Leads; Body 9.9 x 7.6 mm (LxW max); Pitch 1.27 mm)
3D model W16A (DFP; 16 Leads; Body 9.9 x 7.6 mm (LxW max); Pitch 1.27 mm)
simulation model 7445 (SIMCODE)
signal-integrity model DM5445W
pins: 1 ~{Y}0 (oc), 2 ~{Y}1 (oc), 3 ~{Y}2 (oc), 4 ~{Y}3 (oc), 5 ~{Y}4 (oc), 6 ~{Y}5 (oc), 7 ~{Y}6 (oc), 8 GND (power), 9 ~{Y}7 (oc), 10 ~{Y}8 (oc), 11 ~{Y}9 (oc), 12 D (in), 13 C (in), 14 B (in), 15 A (in), 16 VCC (power)

## DM7445N
designator U?
BCD-To-Decimal Decoder/Driver; Note: Generic Simulation model provided.
footprint N16E (DIP, 16-Leads, Row Spacing 7.62mm, Pitch 2.54mm, Body 19.3x6.35mm)
3D model N16E (DIP, 16-Pin, Row Spacing 7.62 mm, Pitch 2.54 mm)
simulation model 7445 (SIMCODE)
signal-integrity model DM7445N
pins: 1 ~{Y}0 (oc), 2 ~{Y}1 (oc), 3 ~{Y}2 (oc), 4 ~{Y}3 (oc), 5 ~{Y}4 (oc), 6 ~{Y}5 (oc), 7 ~{Y}6 (oc), 8 GND (power), 9 ~{Y}7 (oc), 10 ~{Y}8 (oc), 11 ~{Y}9 (oc), 12 D (in), 13 C (in), 14 B (in), 15 A (in), 16 VCC (power)

## DM54145J
designator U?
BCD-To-Decimal Decoder/Driver; Note: Generic Simulation model provided.
footprint J16A (DIP, 16-Leads, Row Spacing 7.62mm, Pitch 2.54mm, Body 19.56x6.73mm)
3D model N16E (CerDIP, 16-Pin, Row Spacing 7.62 mm, Pitch 2.54 mm)
simulation model 7445 (SIMCODE)
signal-integrity model DM54145J
pins: 1 ~{Y}0 (oc), 2 ~{Y}1 (oc), 3 ~{Y}2 (oc), 4 ~{Y}3 (oc), 5 ~{Y}4 (oc), 6 ~{Y}5 (oc), 7 ~{Y}6 (oc), 8 GND (power), 9 ~{Y}7 (oc), 10 ~{Y}8 (oc), 11 ~{Y}9 (oc), 12 D (in), 13 C (in), 14 B (in), 15 A (in), 16 VCC (power)

## DM54145W
designator U?
BCD-To-Decimal Decoder/Driver; Note: Generic Simulation model provided.
footprint W16A (DFP; 16 Leads; Body 9.9 x 7.6 mm (LxW max); Pitch 1.27 mm)
3D model W16A (DFP; 16 Leads; Body 9.9 x 7.6 mm (LxW max); Pitch 1.27 mm)
simulation model 7445 (SIMCODE)
signal-integrity model DM54145W
pins: 1 ~{Y}0 (oc), 2 ~{Y}1 (oc), 3 ~{Y}2 (oc), 4 ~{Y}3 (oc), 5 ~{Y}4 (oc), 6 ~{Y}5 (oc), 7 ~{Y}6 (oc), 8 GND (power), 9 ~{Y}7 (oc), 10 ~{Y}8 (oc), 11 ~{Y}9 (oc), 12 D (in), 13 C (in), 14 B (in), 15 A (in), 16 VCC (power)

## DM74145N
designator U?
BCD-To-Decimal Decoder/Driver; Note: Generic Simulation model provided.
footprint N16E (DIP, 16-Leads, Row Spacing 7.62mm, Pitch 2.54mm, Body 19.3x6.35mm)
3D model N16E (DIP, 16-Pin, Row Spacing 7.62 mm, Pitch 2.54 mm)
simulation model 7445 (SIMCODE)
signal-integrity model DM74145N
pins: 1 ~{Y}0 (oc), 2 ~{Y}1 (oc), 3 ~{Y}2 (oc), 4 ~{Y}3 (oc), 5 ~{Y}4 (oc), 6 ~{Y}5 (oc), 7 ~{Y}6 (oc), 8 GND (power), 9 ~{Y}7 (oc), 10 ~{Y}8 (oc), 11 ~{Y}9 (oc), 12 D (in), 13 C (in), 14 B (in), 15 A (in), 16 VCC (power)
